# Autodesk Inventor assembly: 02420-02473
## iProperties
Author: Administrator
Shininess: 64.0
Angle Display Precision: 2
Document Length Units: 11272
Document Angle Units: 11286
Document Time Units: 11279
Document Mass Units: 11290
Document Length Units Precision: 3
Document Angle Units Precision: 2
Compacted: True
PropertySet Name: _Private Model Information
Created: 2002-04
Part Number: 02420-02473
Document SubType Name: Assembly
Designer: Administrator
Control State: 0
Master: False
Checked Out: False
PropertySet Name: Design Tracking Control
Density: 0.0
Volumn: 0.0
Area: 0.0
PropertySet Name: Model Information
